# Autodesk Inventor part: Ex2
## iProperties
Author: Administrator
Created: 2001-01
Part Number: Ex2
Document SubType Name: Modeling
Designer: Administrator
Control State: 0
Master: False
Checked Out: False
PropertySet Name: Design Tracking Control
Shininess: 0.0
PropertySet Name: _Private Model Information
Density: 0.0
Volumn: 0.0
Area: 0.0
PropertySet Name: Model Information
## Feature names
1. Extrusion1
2. Extrusion2
3. Extrusion3
4. Extrusion4
